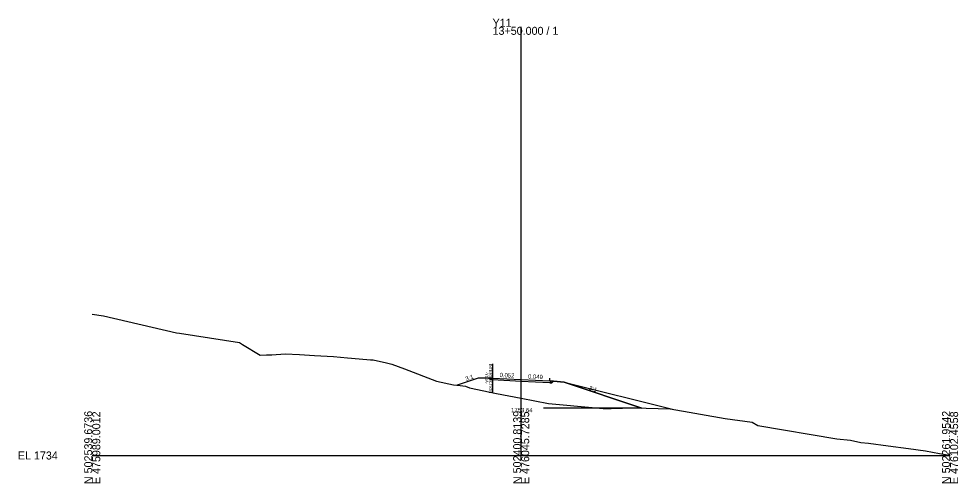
# Model space of a CAD drawing. Extents: x -76 to 353, y -10 to 8186.
# Drawn here: x -25.7 to 302.8, y 6990.3 to 7152.7 of the extents above; entities that cross this region are included whole.
import ezdxf

# ---------------------------------------------------------------- set-up
doc = ezdxf.new("R2010")
doc.units = 0
for name, color, linetype in [('Exist Cross Section Cell', 7, 'Continuous'), ('Exist XS Center Line Elevation Label', 7, 'Continuous'), ('Exist XS Ground Line', 7, 'Continuous'), ('Prop XS Dump Level', 7, 'Continuous'), ('Prop XS Earthwork Shape', 7, 'Continuous'), ('Prop XS EOT Tick Mark', 7, 'Continuous'), ('Prop XS Finish Grade', 7, 'Continuous'), ('Prop XS Finish Grade Earthwork', 7, 'Continuous'), ('Prop XS Finish Grade Pavement', 7, 'Continuous'), ('Prop XS Pvmt Edge Slope', 7, 'Continuous'), ('Prop XS SE Text', 7, 'Continuous'), ('Prop XS Shear Point Label', 7, 'Continuous'), ('Prop XS Shoulder Borrow Shape', 7, 'Continuous'), ('Prop XS Side Slope Text', 7, 'Continuous'), ('Prop XS Subgrade Earthwork', 7, 'Continuous'), ('Scratch_Level_0', 7, 'Continuous'), ('Scratch_Level_4', 7, 'Continuous'), ('Scratch_Level_6', 7, 'Continuous')]:
    doc.layers.add(name, color=color, linetype=linetype)

msp = doc.modelspace()

# ---------------------------------------------------------------- linework, layer by layer
at = {"layer": 'Exist Cross Section Cell'}
for p, q in [((150, 7000), (150, 7149.87)), ((0, 7000), (150, 7000)), ((150, 7000), (300, 7000))]:
    msp.add_line(p, q, dxfattribs=at)
at = {"layer": 'Exist XS Ground Line'}
msp.add_lwpolyline([(0, 7049.37), (3.98, 7048.8), (29.51, 7042.87), (30.55, 7042.73), (51.53, 7039.48), (52.49, 7038.77), (58.7, 7035.12), (60.97, 7035.16), (62.19, 7035.16), (62.79, 7035.2), (67.46, 7035.48), (72.43, 7035.27), (77.67, 7035), (84.32, 7034.66), (89.23, 7034.18), (96.07, 7033.58), (97.25, 7033.47), (98.27, 7033.39), (102.9, 7032.34), (104.75, 7031.97), (109.17, 7030.29), (120.36, 7025.95), (126.3, 7024.72), (128.67, 7024.43), (130.5, 7024.18), (131.9, 7023.62), (141.42, 7021.66), (150, 7020.04), (159.56, 7018.23), (176.08, 7016.71), (178.68, 7016.48), (181.42, 7016.47), (189.5, 7016.65), (202.09, 7016.28), (221.3, 7012.89), (230.84, 7011.63), (232.77, 7010.43), (260.37, 7005.85), (265.12, 7005.39), (268.76, 7004.59), (271.52, 7004.29), (278.29, 7003.38), (285.46, 7002.43), (291.45, 7001.59), (296.26, 7000.67), (299.12, 7000.18), (300, 7000.08)], dxfattribs=at)
at = {"layer": 'Prop XS Dump Level'}
for p, q in [((140, 7027.05), (150, 7026.54)), ((150, 7026.54), (160, 7026.05))]:
    msp.add_line(p, q, dxfattribs=at)
at = {"layer": 'Prop XS Earthwork Shape'}
msp.add_lwpolyline([(135, 7027.01), (127.63, 7024.56), (128.67, 7024.43), (130.5, 7024.18), (131.9, 7023.62), (141.42, 7021.66), (150, 7020.04), (159.56, 7018.23), (176.08, 7016.71), (178.68, 7016.48), (181.42, 7016.47), (189.5, 7016.65), (192.24, 7016.57), (165, 7025.65), (161.3, 7025.95), (160.7, 7025.35), (160, 7025.38), (150, 7025.87), (140, 7026.39), (139.37, 7026.42), (138.74, 7027.04)], close=True, dxfattribs=at)
at = {"layer": 'Prop XS EOT Tick Mark'}
msp.add_line((160, 7026.05), (160, 7027.05), dxfattribs=at)
at = {"layer": 'Prop XS Finish Grade'}
msp.add_line((160, 7026.05), (161.3, 7025.95), dxfattribs=at)
at = {"layer": 'Prop XS Finish Grade Earthwork'}
for p, q in [((161.3, 7025.95), (165, 7025.65)), ((165, 7025.65), (192.24, 7016.57))]:
    msp.add_line(p, q, dxfattribs=at)
at = {"layer": 'Prop XS Finish Grade Pavement'}
for p, q in [((140, 7027.05), (150, 7026.54)), ((150, 7026.54), (160, 7026.05))]:
    msp.add_line(p, q, dxfattribs=at)
at = {"layer": 'Prop XS Pvmt Edge Slope'}
msp.add_line((160, 7026.05), (160.7, 7025.35), dxfattribs=at)
at = {"layer": 'Prop XS Shear Point Label'}
msp.add_line((140, 7032.06), (140, 7022.1), dxfattribs=at)
at = {"layer": 'Prop XS Shoulder Borrow Shape'}
msp.add_lwpolyline([(160.7, 7025.35), (161.3, 7025.95), (160, 7026.05)], close=True, dxfattribs=at)
msp.add_lwpolyline([(160.7, 7025.35), (161.3, 7025.95), (160, 7026.05)], close=True, dxfattribs=at)
at = {"layer": 'Prop XS Subgrade Earthwork'}
for p, q in [((150, 7025.87), (140, 7026.39)), ((160, 7025.38), (150, 7025.87)), ((160, 7025.38), (160.7, 7025.35)), ((160.7, 7025.35), (161.3, 7025.95))]:
    msp.add_line(p, q, dxfattribs=at)
at = {"layer": 'Scratch_Level_0'}
for p, q in [((140, 7027.05), (140, 7028.05)), ((135, 7027.01), (127.63, 7024.56)), ((138.74, 7027.04), (135, 7027.01)), ((140, 7027.05), (138.74, 7027.04)), ((139.37, 7026.42), (138.74, 7027.04)), ((140, 7027.05), (139.37, 7026.42)), ((140, 7026.39), (139.37, 7026.42))]:
    msp.add_line(p, q, dxfattribs=at)
msp.add_lwpolyline([(140, 7027.05), (139.37, 7026.42), (138.74, 7027.04)], close=True, dxfattribs=at)
msp.add_lwpolyline([(140, 7027.05), (139.37, 7026.42), (138.74, 7027.04)], close=True, dxfattribs=at)
at = {"layer": 'Scratch_Level_4'}
msp.add_line((192.24, 7016.57), (157.82, 7016.57), dxfattribs=at)
at = {"layer": 'Scratch_Level_6'}
msp.add_line((165, 7025.65), (203.4, 7016.05), dxfattribs=at)

# ---------------------------------------------------------------- texts
at = {"layer": 'Exist Cross Section Cell'}
for s, p in [('Y11', (140, 7149.87)), ('13+50.000 / 1', (140, 7147.07)), ('EL 1734', (-26, 6998.6))]:
    msp.add_text(s, height=2.8, dxfattribs=at).set_placement(p)
for s, p in [('N 502539.6736', (0, 6990)), ('E 475989.0012', (2.8, 6990)), ('N 502400.8139', (150, 6990)), ('E 476045.7285', (152.8, 6990)), ('N 502261.9542', (300, 6990)), ('E 476102.4558', (302.8, 6990))]:
    msp.add_text(s, height=2.8, rotation=90, dxfattribs=at).set_placement(p)
at = {"layer": 'Exist XS Center Line Elevation Label'}
msp.add_text('1753.64', height=1.5, dxfattribs=at).set_placement((146.49, 7015.14))
at = {"layer": 'Prop XS Dump Level'}
msp.add_text('Case1', height=0.04, dxfattribs=at).set_placement((165, 7025.61))
at = {"layer": 'Prop XS SE Text'}
for s, rotation, p in [('0.052', 357.0484, (142.43, 7027.43)), ('0.049', 357.2092, (152.37, 7026.92))]:
    msp.add_text(s, height=1.5, rotation=rotation, dxfattribs=at).set_placement(p)
at = {"layer": 'Prop XS Shear Point Label'}
for s, p in [('INTERSECTION', (138.79, 7032.06)), ('-Y11A-', (137.49, 7029.29))]:
    msp.add_text(s, height=1, rotation=270, dxfattribs=at).set_placement(p)
at = {"layer": 'Prop XS Side Slope Text'}
msp.add_text('3:1', height=1.5, rotation=341.5651, dxfattribs=at).set_placement((173.54, 7023.03))
at = {"layer": 'Scratch_Level_0'}
msp.add_text('3:1', height=1.5, rotation=18.4349, dxfattribs=at).set_placement((130.77, 7026.05))
msp.add_text('Case1', height=0.04, dxfattribs=at).set_placement((135, 7026.97))

doc.saveas('drawing.dxf')
